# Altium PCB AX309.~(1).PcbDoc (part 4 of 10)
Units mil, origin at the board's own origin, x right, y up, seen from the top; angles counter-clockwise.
Board outline 5185 x 3614 mil, 4 copper layers (Top Layer, GND, Mid-Layer 1, Bottom Layer); 191 components, 352 nets, 1106 pads, 425 vias.
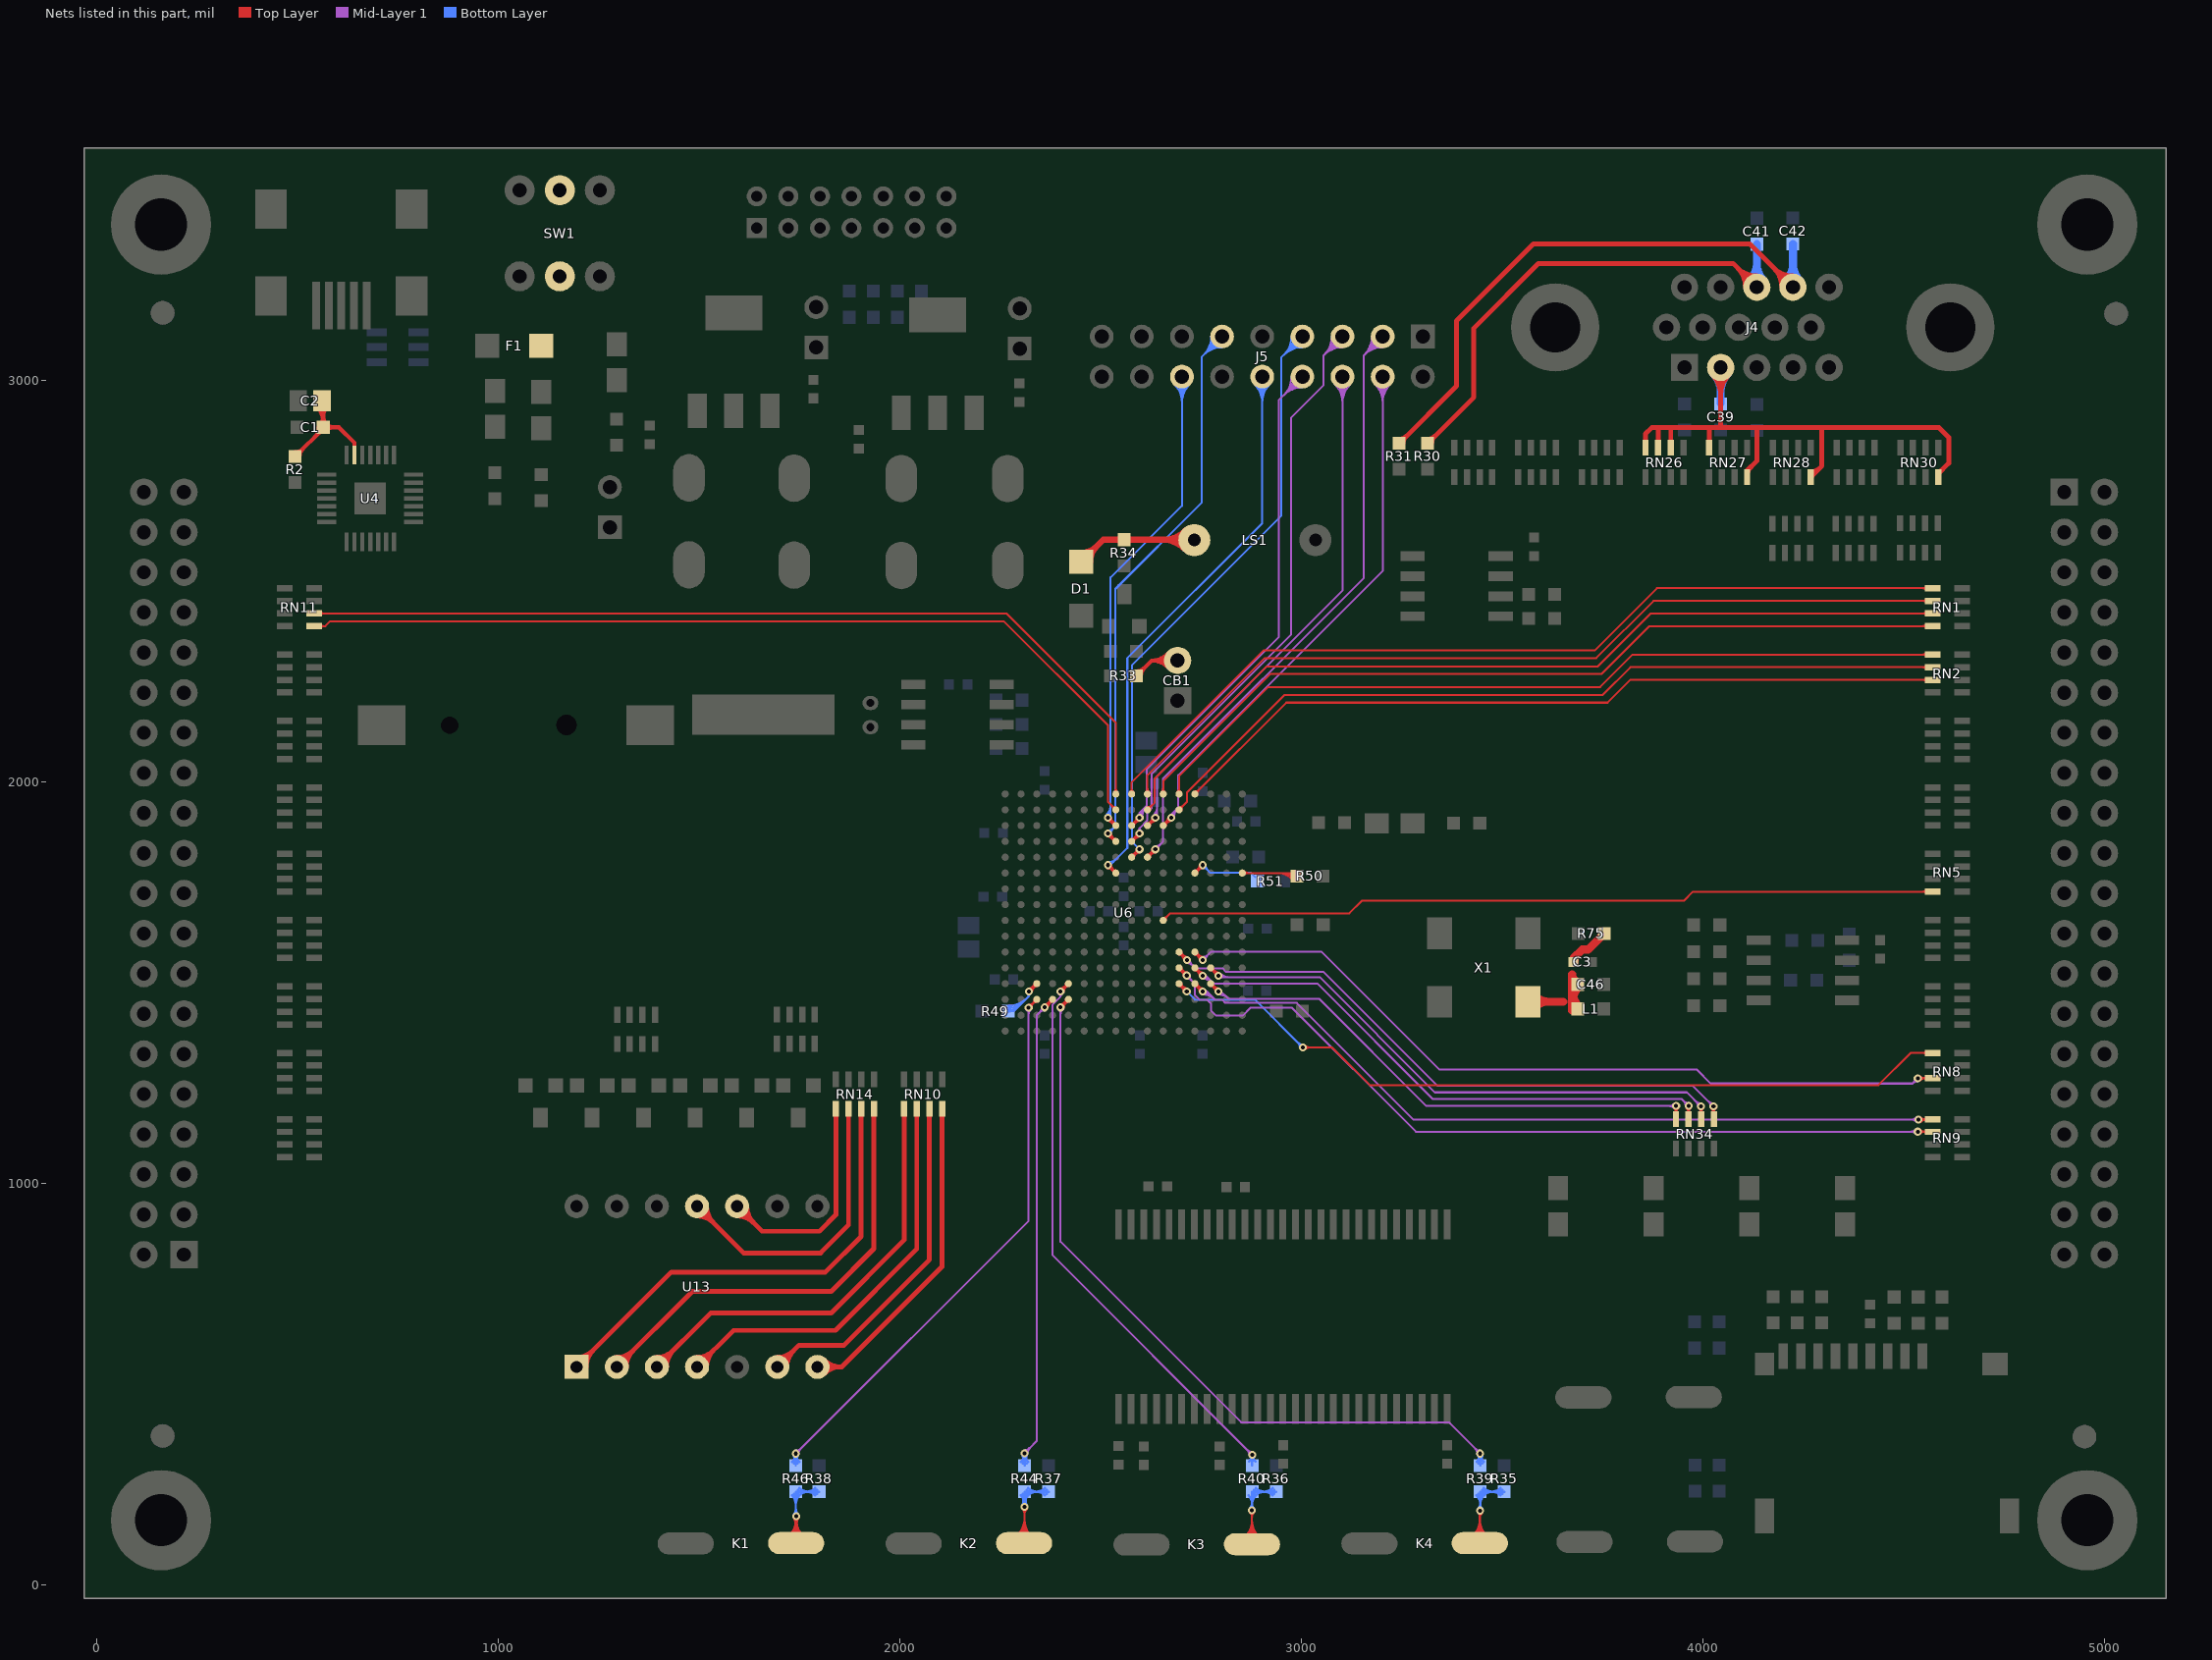
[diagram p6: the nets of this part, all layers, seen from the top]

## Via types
v1: diameter 20, hole 10, Top Layer to Bottom Layer, 328 vias
v2: diameter 30, hole 15, Top Layer to Bottom Layer, 95 vias
v3: diameter 40, hole 20, Top Layer to Bottom Layer, 2 vias

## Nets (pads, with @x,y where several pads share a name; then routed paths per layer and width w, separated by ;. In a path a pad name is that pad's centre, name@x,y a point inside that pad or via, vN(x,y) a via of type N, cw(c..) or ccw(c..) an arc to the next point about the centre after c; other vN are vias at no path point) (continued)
GREEN: C39.1 J4.2 RN26.2 RN26.3 RN26.4 RN27.4 RN27.8 RN28.8 RN30.8 | length 1876.1
  Top Layer w12: RN26.4@3857.65,2832 3857.65,2866.65 3873,2882 4135,2882 ; RN26.3@3889.15,2832 3889.15,2880.15 ; RN26.2@3920.65,2832 3920.65,2881.65 ; RN27.4@4016.37,2832 4016.37,2880.37 ; J4.2@4025.2,3012.2 cw(c3977.4,2964.4) 4045,2964.4 cw(c4112.6,2964.4) J4.2@4064.8,3012.2 ; J4.2@4033.69,3020.69 cw(c4006.37,2993.37) 4045,2993.37 cw(c4083.63,2993.37) J4.2@4056.31,3020.69 ; 4045,2883 J4.2@4045,3032 ; RN27.8@4110.86,2758.85 4110.86,2774.86 4135,2799 4135,2882 ; RN27.8@4112.73,2770.66 cw(c4127.38,2770.66) 4117.02,2781.02 ; RN28.8@4269.57,2758.85 4297,2786.28 4297,2882 ; RN28.8@4269.57,2760.54 ccw(c4269.57,2764.6) RN28.8@4272.45,2761.73 ; RN28.8@4269.57,2772.54 ccw(c4269.57,2805.57) 4292.93,2782.21 ; RN30.8@4587,2758.85 4587,2767.5 4613,2793.5 4613,2858 4589,2882 4297,2882 ; RN30.8@4587,2772.54 ccw(c4587,2784.69) 4595.59,2776.1 ; 4135,2882 4297,2882
  Bottom Layer w20: J4.2@4028.03,3015.03 cw(c3987.06,2974.06) 4045,2974.06 cw(c4102.94,2974.06) J4.2@4061.97,3015.03 ; C39.1@4045,2943 J4.2@4045,3032
H11: J5.10 U6.H11 | length 1849.8
  Top Layer w5: v1@2517.62,1784.68 cw(c2514.91,1764.7) U6.H11@2532.37,1774.78 ; v1@2518.29,1789.63 cw(c2516.64,1777.47) 2527.27,1783.61 ; v1@2518.63,1784.61 cw(c2518.63,1766.5) 2531.43,1779.31 cw(c2544.24,1792.11) v1@2526.13,1792.11 ; v1(2518.63,1792.11) U6.H11@2538.32,1772.43 ; v1@2520.6,1784.87 cw(c2522.41,1778.21) 2528.39,1781.66 ; v1@2521.11,1792.45 ccw(c2533.27,1794.1) 2527.13,1783.47 ; v1@2526.06,1793.12 ccw(c2546.04,1795.83) U6.H11@2535.96,1778.37 ; 2529.08,1782.35 cw(c2532.53,1788.33) v1@2525.87,1790.14 ; U6.H11@2531.96,1772.43 ccw(c2516.61,1772.43) 2527.46,1783.28 ccw(c2538.32,1794.13) U6.H11@2538.32,1778.78 ; v1@2525.87,1790.17 ccw(c2532.7,1788.34) 2526.58,1784.81 cw(c2532.7,1788.34) v1@2525.87,1790.17 ; v1@2520.57,1784.87 cw(c2522.4,1778.04) 2525.93,1784.16 ccw(c2522.4,1778.04) v1@2520.57,1784.87
  Bottom Layer w5: v1(2518.63,1792.11) 2524.11,1792.11 2567,1835 2567,2308 2903,2644 J5.10@2903,3009.17 ; v1@2518.63,1794.61 ccw(c2518.63,1813.88) 2532.26,1800.26 ; v1@2518.63,1799.61 ccw(c2518.63,1830.95) 2540.79,1808.79 ; J5.10@2883.89,2990.06 cw(c2837.75,2943.92) 2903,2943.92 cw(c2968.25,2943.92) J5.10@2922.11,2990.06 ; J5.10@2887.42,2993.6 cw(c2849.82,2955.99) 2903,2955.99 cw(c2956.18,2955.99) J5.10@2918.58,2993.6 ; J5.10@2890.96,2997.13 cw(c2861.89,2968.07) 2903,2968.07 cw(c2944.11,2968.07) J5.10@2915.04,2997.13
H13: J5.11 U6.H13 | length 1815.1
  Top Layer w5: v1@2517.62,1863.42 cw(c2514.91,1843.44) U6.H13@2532.37,1853.52 ; v1@2518.29,1868.37 cw(c2516.64,1856.21) 2527.27,1862.35 ; v1@2518.63,1863.35 cw(c2518.63,1845.24) 2531.43,1858.05 cw(c2544.24,1870.85) v1@2526.13,1870.85 ; v1(2518.63,1870.85) U6.H13@2538.32,1851.17 ; v1@2520.6,1863.61 cw(c2522.41,1856.95) 2528.39,1860.4 ; v1@2521.11,1871.19 ccw(c2533.27,1872.84) 2527.13,1862.21 ; v1@2526.06,1871.86 ccw(c2546.04,1874.57) U6.H13@2535.96,1857.11 ; 2529.08,1861.09 cw(c2532.53,1867.07) v1@2525.87,1868.88 ; U6.H13@2531.96,1851.17 ccw(c2516.61,1851.17) 2527.46,1862.02 ccw(c2538.32,1872.87) U6.H13@2538.32,1857.52 ; v1@2525.87,1868.91 ccw(c2532.7,1867.08) 2526.58,1863.55 cw(c2532.7,1867.08) v1@2525.87,1868.91 ; v1@2520.57,1863.61 cw(c2522.4,1856.78) 2525.93,1862.9 ccw(c2522.4,1856.78) v1@2520.57,1863.61
  Bottom Layer w5: v1(2518.63,1870.85) 2537,1889.22 2537,2480 2752,2695 2752,3058.17 J5.11@2803,3109.17 ; v1@2518.63,1878.35 ccw(c2518.63,1896.46) 2531.43,1883.65 ccw(c2544.24,1870.85) v1@2526.13,1870.85 ; J5.11@2775.97,3109.17 cw(c2710.72,3109.17) 2756.86,3063.03 cw(c2803,3016.9) J5.11@2803,3082.15 ; J5.11@2780.97,3109.17 cw(c2727.79,3109.17) 2765.4,3071.57 cw(c2803,3033.97) J5.11@2803,3087.15 ; J5.11@2785.97,3109.17 cw(c2744.86,3109.17) 2773.93,3080.11 cw(c2803,3051.04) J5.11@2803,3092.15
H14: J5.14 U6.H14 | length 1671.3
  Top Layer w5: v1@2517.62,1902.79 cw(c2514.91,1882.81) U6.H14@2532.37,1892.89 ; v1@2518.29,1907.74 cw(c2516.64,1895.58) 2527.27,1901.72 ; v1@2518.63,1902.72 cw(c2518.63,1884.61) 2531.43,1897.42 cw(c2544.24,1910.22) v1@2526.13,1910.22 ; v1(2518.63,1910.22) U6.H14@2538.32,1890.54 ; v1@2520.6,1902.98 cw(c2522.41,1896.32) 2528.39,1899.77 ; v1@2521.11,1910.56 ccw(c2533.27,1912.21) 2527.13,1901.58 ; v1@2525.87,1908.25 ccw(c2532.53,1906.44) 2529.08,1900.46 ; v1@2526.06,1911.23 ccw(c2546.04,1913.94) U6.H14@2535.96,1896.48 ; U6.H14@2531.96,1890.54 ccw(c2516.61,1890.54) 2527.46,1901.39 ccw(c2538.32,1912.24) U6.H14@2538.32,1896.89 ; v1@2520.57,1902.98 cw(c2522.4,1896.15) 2525.93,1902.27 ccw(c2522.4,1896.15) v1@2520.57,1902.98 ; v1@2525.87,1908.28 ccw(c2532.7,1906.45) 2526.58,1902.92 cw(c2532.7,1906.45) v1@2525.87,1908.28
  Bottom Layer w5: v1@2513.33,1915.52 ccw(c2485.14,1943.71) 2525,1943.71 ; v1@2516.86,1911.99 ccw(c2497.21,1931.64) 2525,1931.64 ; v1(2518.63,1910.22) 2525,1916.59 2525,2509 2703,2687 J5.14@2703,3009.17 ; v1@2520.4,1908.45 ccw(c2509.28,1919.57) 2525,1919.57 ; J5.14@2683.89,2990.06 cw(c2637.75,2943.92) 2703,2943.92 cw(c2768.25,2943.92) J5.14@2722.11,2990.06 ; J5.14@2687.42,2993.6 cw(c2649.82,2955.99) 2703,2955.99 cw(c2756.18,2955.99) J5.14@2718.58,2993.6 ; J5.14@2690.96,2997.13 cw(c2661.89,2968.07) 2703,2968.07 cw(c2744.11,2968.07) J5.14@2715.04,2997.13
H15: RN11.5 U6.H15 | length 2352.5
  Top Layer w5: RN11.5@541.15,2387.51 568.84,2387.51 580.32,2399 2260,2399 2519,2140 2519,1949.22 U6.H15@2538.32,1929.91 ; RN11.5@556.76,2383.71 cw(c565.93,2374.54) 565.93,2387.51 cw(c565.93,2400.49) RN11.5@556.76,2391.31 ; U6.H15@2531.96,1929.91 ccw(c2516.61,1929.91) 2527.46,1940.76 ccw(c2538.32,1951.61) U6.H15@2538.32,1936.26
H16: RN11.6 U6.H16 | length 2331.9
  Top Layer w5: RN11.6@541.15,2419.01 2265.99,2419.01 2538.32,2146.68 U6.H16@2538.32,1969.28 ; RN11.6@556.76,2415.21 cw(c565.93,2406.03) 565.93,2419.01 cw(c565.93,2431.98) RN11.6@556.76,2422.81 ; U6.H16@2533.82,1973.77 ccw(c2522.96,1984.63) 2538.32,1984.63 ccw(c2553.67,1984.63) U6.H16@2542.81,1973.77
HSWAPEN: R49.1 U6.C4 | length 421.8
  Top Layer w5: v1@2320.77,1484.58 ccw(c2318.06,1504.56) U6.C4@2335.52,1494.48 ; v1@2321.44,1479.63 ccw(c2319.79,1491.79) 2330.42,1485.65 ; v1(2321.78,1477.15) U6.C4@2341.46,1496.83 ; v1@2321.78,1484.65 ccw(c2321.78,1502.76) 2334.58,1489.95 ccw(c2347.39,1477.15) v1@2329.28,1477.15 ; v1@2323.75,1484.39 ccw(c2325.56,1491.05) 2331.54,1487.6 ; v1@2324.26,1476.81 cw(c2336.42,1475.16) 2330.28,1485.79 ; v1@2329.21,1476.14 cw(c2349.19,1473.43) U6.C4@2339.11,1490.89 ; 2332.23,1486.91 ccw(c2335.68,1480.93) v1@2329.02,1479.12 ; U6.C4@2335.11,1496.83 cw(c2319.76,1496.83) 2330.61,1485.98 cw(c2341.46,1475.13) U6.C4@2341.46,1490.48 ; v1@2329.02,1479.09 cw(c2335.85,1480.92) 2329.73,1484.45 ccw(c2335.85,1480.92) v1@2329.02,1479.09 ; v1@2323.72,1484.39 ccw(c2325.55,1491.22) 2329.08,1485.1 cw(c2325.55,1491.22) v1@2323.72,1484.39
  Bottom Layer w5: R49.1@2270,1426.5 ccw(c2270,1456.68) 2291.34,1435.34 ; R49.1@2270,1428 2284,1428 2321.78,1465.78 ; R49.1@2270,1431.5 ccw(c2270,1473.75) 2299.87,1443.87 ; R49.1@2270,1436.5 ccw(c2270,1490.82) 2308.41,1452.41 ; R49.1@2270,1441.5 ccw(c2270,1507.89) 2316.95,1460.95 ; v1@2318.83,1470.25 cw(c2316.91,1465.78) 2321.78,1465.78 ; v1(2321.78,1477.15) 2321.78,1465.78 ; v1@2324.73,1470.25 ccw(c2326.65,1465.78) 2321.78,1465.78
J12: J5.7 U6.J12 | length 1891.4
  Top Layer w5: U6.J12@2577.68,1811.8 v1(2597.37,1831.48) ; U6.J12@2577.68,1818.15 ccw(c2577.68,1833.5) 2588.54,1822.65 ccw(c2599.39,1811.8) U6.J12@2584.04,1811.8 ; U6.J12@2580.04,1817.74 ccw(c2569.96,1835.2) v1@2589.94,1832.49 ; U6.J12@2583.63,1814.15 cw(c2601.09,1804.07) v1@2598.38,1824.05 ; 2586.92,1821.72 ccw(c2583.47,1827.7) v1@2590.13,1829.51 ; 2587.61,1821.03 cw(c2593.59,1817.58) v1@2595.4,1824.24 ; 2588.73,1822.98 cw(c2599.36,1816.84) v1@2597.71,1829 ; 2588.87,1822.84 ccw(c2582.73,1833.47) v1@2594.89,1831.82 ; v1@2589.87,1831.48 cw(c2571.76,1831.48) 2584.57,1818.68 cw(c2597.37,1805.87) v1@2597.37,1823.98 ; 2589.42,1824.18 ccw(c2583.3,1827.71) 2590.13,1829.54 cw(c2583.3,1827.71) 2589.42,1824.18 ; 2590.07,1823.53 cw(c2593.6,1817.41) 2595.43,1824.24 ccw(c2593.6,1817.41) 2590.07,1823.53
  Bottom Layer w5: v1(2597.37,1831.48) 2579,1849.85 2579,2291 2950,2662 2950,3056.17 J5.7@3003,3109.17 ; J5.7@2975.97,3109.17 cw(c2910.72,3109.17) 2956.86,3063.03 cw(c3003,3016.9) J5.7@3003,3082.15 ; J5.7@2980.97,3109.17 cw(c2927.79,3109.17) 2965.4,3071.57 cw(c3003,3033.97) J5.7@3003,3087.15 ; J5.7@2985.97,3109.17 cw(c2944.86,3109.17) 2973.93,3080.11 cw(c3003,3051.04) J5.7@3003,3092.15
J13: J5.5 U6.J13 | length 1895.4
  Top Layer w5: U6.J13@2577.68,1851.17 v1(2597.37,1870.85) ; U6.J13@2577.68,1857.52 ccw(c2577.68,1872.87) 2588.54,1862.02 ccw(c2599.39,1851.17) U6.J13@2584.04,1851.17 ; U6.J13@2580.04,1857.11 ccw(c2569.96,1874.57) v1@2589.94,1871.86 ; U6.J13@2583.63,1853.52 cw(c2601.09,1843.44) v1@2598.38,1863.42 ; 2586.92,1861.09 ccw(c2583.47,1867.07) v1@2590.13,1868.88 ; 2587.61,1860.4 cw(c2593.59,1856.95) v1@2595.4,1863.61 ; 2588.73,1862.35 cw(c2599.36,1856.21) v1@2597.71,1868.37 ; 2588.87,1862.21 ccw(c2582.73,1872.84) v1@2594.89,1871.19 ; v1@2589.87,1870.85 cw(c2571.76,1870.85) 2584.57,1858.05 cw(c2597.37,1845.24) v1@2597.37,1863.35 ; v1@2590.13,1868.91 cw(c2583.3,1867.08) 2589.42,1863.55 ccw(c2583.3,1867.08) v1@2590.13,1868.91 ; 2590.07,1862.9 cw(c2593.6,1856.78) 2595.43,1863.61 ccw(c2593.6,1856.78) 2590.07,1862.9
  Mid-Layer 1 w5: v1@2593.4,1877.21 ccw(c2588.94,1884.37) 2597.37,1884.37 ; v1(2597.37,1870.85) 2597.37,1884.37 ; v1@2601.34,1877.21 cw(c2605.81,1884.37) 2597.37,1884.37 ; J5.5@3075.97,3109.17 cw(c3010.72,3109.17) 3056.86,3063.03 cw(c3103,3016.9) J5.5@3103,3082.15 ; J5.5@3080.97,3109.17 cw(c3027.79,3109.17) 3065.4,3071.57 cw(c3103,3033.97) J5.5@3103,3087.15 ; J5.5@3085.97,3109.17 cw(c3044.86,3109.17) 3073.93,3080.11 cw(c3103,3051.04) J5.5@3103,3092.15 ; J5.5@3103,3109.17 3055,3061.17 3055,2987 2975,2907 2975,2367 2628,2020 2628,1934 2616,1922 2616,1903 2597.37,1884.37
J14: J5.8 U6.J14 | length 1783.8
  Top Layer w5: U6.J14@2577.68,1890.54 v1(2597.37,1910.22) ; U6.J14@2577.68,1896.89 ccw(c2577.68,1912.24) 2588.54,1901.39 ccw(c2599.39,1890.54) U6.J14@2584.04,1890.54 ; U6.J14@2580.04,1896.48 ccw(c2569.96,1913.94) v1@2589.94,1911.23 ; U6.J14@2583.63,1892.89 cw(c2601.09,1882.81) v1@2598.38,1902.79 ; 2586.92,1900.46 ccw(c2583.47,1906.44) v1@2590.13,1908.25 ; 2587.61,1899.77 cw(c2593.59,1896.32) v1@2595.4,1902.98 ; 2588.73,1901.72 cw(c2599.36,1895.58) v1@2597.71,1907.74 ; 2588.87,1901.58 ccw(c2582.73,1912.21) v1@2594.89,1910.56 ; v1@2589.87,1910.22 cw(c2571.76,1910.22) 2584.57,1897.42 cw(c2597.37,1884.61) v1@2597.37,1902.72 ; 2589.42,1902.92 ccw(c2583.3,1906.45) 2590.13,1908.28 cw(c2583.3,1906.45) 2589.42,1902.92 ; 2590.07,1902.27 cw(c2593.6,1896.15) 2595.43,1902.98 ccw(c2593.6,1896.15) 2590.07,1902.27
  Mid-Layer 1 w5: v1@2594.01,1916.93 ccw(c2591.28,1922.37) 2597.37,1922.37 ; v1@2594.89,1909.95 cw(c2613.54,1912) 2600.27,1925.27 ; v1(2597.37,1910.22) 2597.37,1922.37 ; v1@2599.86,1910.5 cw(c2626.8,1913.46) 2607.63,1932.63 ; v1@2600.73,1916.93 cw(c2603.46,1922.37) 2597.37,1922.37 ; v1@2604.83,1911.04 cw(c2640.07,1914.92) 2615,1940 ; J5.8@2975.97,3009.17 cw(c2910.72,3009.17) 2956.86,2963.03 cw(c3003,2916.9) J5.8@3003,2982.15 ; J5.8@2980.97,3009.17 cw(c2927.79,3009.17) 2965.4,2971.57 cw(c3003,2933.97) J5.8@3003,2987.15 ; J5.8@2985.97,3009.17 cw(c2944.86,3009.17) 2973.93,2980.11 cw(c3003,2951.04) J5.8@3003,2992.15 ; J5.8@3003,3009.17 2944,2950.17 2944,2360 2615,2031 2615,1940 ; 2597.37,1922.37 2615,1940
J16: RN1.1 U6.J16 | length 2269.4
  Top Layer w5: U6.J16@2573.19,1973.77 ccw(c2562.33,1984.63) 2577.68,1984.63 ccw(c2593.04,1984.63) U6.J16@2582.18,1973.77 ; U6.J16@2577.68,1969.28 2577.68,1998.68 2906,2327 3731,2327 3886,2482 RN1.1@4573,2482 ; RN1.1@4557.39,2478.2 ccw(c4548.22,2469.03) 4548.22,2482 ccw(c4548.22,2494.97) RN1.1@4557.39,2485.8
K12: J5.3 U6.K12 | length 1971.2
  Top Layer w5: U6.K12@2617.06,1811.8 v1(2636.74,1831.48) ; U6.K12@2617.06,1818.15 ccw(c2617.06,1833.5) 2627.91,1822.65 ccw(c2638.76,1811.8) U6.K12@2623.41,1811.8 ; U6.K12@2619.41,1817.74 ccw(c2609.33,1835.2) v1@2629.31,1832.49 ; U6.K12@2623,1814.15 cw(c2640.46,1804.07) v1@2637.75,1824.05 ; 2626.29,1821.72 ccw(c2622.84,1827.7) v1@2629.5,1829.51 ; 2626.98,1821.03 cw(c2632.96,1817.58) v1@2634.77,1824.24 ; 2628.1,1822.98 cw(c2638.73,1816.84) v1@2637.08,1829 ; 2628.24,1822.84 ccw(c2622.1,1833.47) v1@2634.26,1831.82 ; v1@2629.24,1831.48 cw(c2611.13,1831.48) 2623.94,1818.68 cw(c2636.74,1805.87) v1@2636.74,1823.98 ; 2628.79,1824.18 ccw(c2622.67,1827.71) 2629.5,1829.54 cw(c2622.67,1827.71) 2628.79,1824.18 ; 2629.44,1823.53 cw(c2632.97,1817.41) 2634.8,1824.24 ccw(c2632.97,1817.41) 2629.44,1823.53
  Mid-Layer 1 w5: v1(2636.74,1831.48) 2656,1850.74 2656,2008 3156,2508 3156,3062.17 J5.3@3203,3109.17 ; v1@2636.74,1838.98 ccw(c2636.74,1857.09) 2649.54,1844.28 ccw(c2662.35,1831.48) v1@2644.24,1831.48 ; J5.3@3175.97,3109.17 cw(c3110.72,3109.17) 3156.86,3063.03 cw(c3203,3016.9) J5.3@3203,3082.15 ; J5.3@3180.97,3109.17 cw(c3127.79,3109.17) 3165.4,3071.57 cw(c3203,3033.97) J5.3@3203,3087.15 ; J5.3@3185.97,3109.17 cw(c3144.86,3109.17) 3173.93,3080.11 cw(c3203,3051.04) J5.3@3203,3092.15
K14: J5.6 U6.K14 | length 1764.4
  Top Layer w5: U6.K14@2617.06,1890.54 v1(2636.74,1910.22) ; U6.K14@2617.06,1896.89 ccw(c2617.06,1912.24) 2627.91,1901.39 ccw(c2638.76,1890.54) U6.K14@2623.41,1890.54 ; U6.K14@2619.41,1896.48 ccw(c2609.33,1913.94) v1@2629.31,1911.23 ; U6.K14@2623,1892.89 cw(c2640.46,1882.81) v1@2637.75,1902.79 ; 2626.29,1900.46 ccw(c2622.84,1906.44) v1@2629.5,1908.25 ; 2626.98,1899.77 cw(c2632.96,1896.32) v1@2634.77,1902.98 ; 2628.1,1901.72 cw(c2638.73,1895.58) v1@2637.08,1907.74 ; 2628.24,1901.58 ccw(c2622.1,1912.21) v1@2634.26,1910.56 ; v1@2629.24,1910.22 cw(c2611.13,1910.22) 2623.94,1897.42 cw(c2636.74,1884.61) v1@2636.74,1902.72 ; 2628.79,1902.92 ccw(c2622.67,1906.45) 2629.5,1908.28 cw(c2622.67,1906.45) 2628.79,1902.92 ; 2629.44,1902.27 cw(c2632.97,1896.15) 2634.8,1902.98 ccw(c2632.97,1896.15) 2629.44,1902.27
  Mid-Layer 1 w5: v1@2631.44,1915.52 ccw(c2608.35,1938.61) 2641,1938.61 ; v1@2634.97,1911.99 ccw(c2620.42,1926.54) 2641,1926.54 ; v1(2636.74,1910.22) 2641,1914.48 2641,2014 3103,2476 J5.6@3103,3009.17 ; J5.6@3083.89,2990.06 cw(c3037.75,2943.92) 3103,2943.92 cw(c3168.25,2943.92) J5.6@3122.11,2990.06 ; J5.6@3087.42,2993.6 cw(c3049.82,2955.99) 3103,2955.99 cw(c3156.18,2955.99) J5.6@3118.58,2993.6 ; J5.6@3090.96,2997.13 cw(c3061.89,2968.07) 3103,2968.07 cw(c3144.11,2968.07) J5.6@3115.04,2997.13
K15: RN1.3 U6.K15 | length 2238.3
  Top Layer w5: U6.K15@2617.06,1929.91 2635,1947.85 2635,2008 2914,2287 3739,2287 3871.01,2419.01 RN1.3@4573,2419.01 ; U6.K15@2617.06,1936.26 ccw(c2617.06,1951.61) 2627.91,1940.76 ccw(c2638.76,1929.91) U6.K15@2623.41,1929.91 ; RN1.3@4557.39,2415.21 ccw(c4548.22,2406.03) 4548.22,2419.01 ccw(c4548.22,2431.98) RN1.3@4557.39,2422.81
K16: RN1.2 U6.K16 | length 2227.2
  Top Layer w5: U6.K16@2612.56,1973.77 ccw(c2601.7,1984.63) 2617.06,1984.63 ccw(c2632.41,1984.63) U6.K16@2621.55,1973.77 ; U6.K16@2617.06,1969.28 2617.06,2016.06 2909,2308 3735,2308 3877.5,2450.5 RN1.2@4573,2450.5 ; RN1.2@4557.39,2446.7 ccw(c4548.22,2437.53) 4548.22,2450.5 ccw(c4548.22,2463.48) RN1.2@4557.39,2454.3
KEY1: R46.1 U6.C3 | length 1658.6
  Top Layer w5: v1(2321,1437) U6.C3@2341.46,1457.46 ; v1@2321,1444.5 ccw(c2321,1462.61) 2333.8,1449.8 ccw(c2346.61,1437) v1@2328.5,1437 ; U6.C3@2335.11,1457.46 cw(c2319.76,1457.46) 2330.61,1446.61 cw(c2341.46,1435.76) U6.C3@2341.46,1451.11
  Mid-Layer 1 w5: v1(1741,326) 2321,906 v1(2321,1437) ; v1@1741,333.5 ccw(c1741,351.61) 1753.8,338.8 ccw(c1766.61,326) v1@1748.5,326 ; v1@2315.7,1431.7 cw(c2302.89,1418.89) 2321,1418.89 cw(c2339.11,1418.89) v1@2326.3,1431.7
  Bottom Layer w6: R46.1@1732.11,305.49 ccw(c1712.89,326) v1(1741,326) ; v1@1735.36,321.85 cw(c1726,314.95) 1737.23,311.94 cw(c1748.47,308.93) v1@1743.81,319.59 ; v1@1736.05,321.05 cw(c1724.1,309.1) 1741,309.1 cw(c1757.9,309.1) v1@1745.95,321.05 ; R46.1@1736.21,301.11 ccw(c1725.86,312.15) 1741,312.15 ccw(c1756.14,312.15) R46.1@1745.79,301.11 ; v1@1738.19,319.59 cw(c1733.53,308.93) 1744.77,311.94 cw(c1756,314.95) v1@1746.64,321.85 ; R46.1@1741,296 v1(1741,326) ; R46.1@1749.89,305.49 cw(c1769.11,326) v1(1741,326)
KEY2: R44.1 U6.D3 | length 1546.1
  Top Layer w5: v1@2360.14,1445.21 ccw(c2357.43,1465.19) U6.D3@2374.89,1455.11 ; v1@2360.81,1440.26 ccw(c2359.16,1452.42) 2369.79,1446.28 ; v1(2361.15,1437.78) U6.D3@2380.83,1457.46 ; v1@2361.15,1445.28 ccw(c2361.15,1463.39) 2373.95,1450.58 ccw(c2386.76,1437.78) v1@2368.65,1437.78 ; v1@2363.63,1437.44 cw(c2375.79,1435.79) 2369.65,1446.42 ; v1@2368.39,1439.75 cw(c2375.05,1441.56) 2371.6,1447.54 ; v1@2368.58,1436.77 cw(c2388.56,1434.06) U6.D3@2378.48,1451.52 ; 2370.91,1448.23 cw(c2364.93,1451.68) v1@2363.12,1445.02 ; U6.D3@2374.48,1457.46 cw(c2359.13,1457.46) 2369.98,1446.61 cw(c2380.83,1435.76) U6.D3@2380.83,1451.11 ; v1@2363.09,1445.02 ccw(c2364.92,1451.85) 2368.45,1445.73 cw(c2364.92,1451.85) v1@2363.09,1445.02 ; v1@2368.39,1439.72 cw(c2375.22,1441.55) 2369.1,1445.08 ccw(c2375.22,1441.55) v1@2368.39,1439.72
  Mid-Layer 1 w5: 2323.37,339.37 2341.46,357.46 2341.46,1418.09 v1(2361.15,1437.78) ; v1@2353.65,1437.78 cw(c2335.54,1437.78) 2348.35,1424.98 cw(c2361.15,1412.17) v1@2361.15,1430.28
  Mid-Layer 1 w6: v1(2311,327) 2323.37,339.37 ; v1@2311,334 ccw(c2311,350.9) 2322.95,338.95 ccw(c2334.9,327) v1@2318,327
  Bottom Layer w6: R44.1@2301.89,305.27 ccw(c2280.54,327) v1(2311,327) ; v1@2305.12,323.2 cw(c2293.15,315.46) 2306.92,311.77 cw(c2320.69,308.08) v1@2314.19,320.77 ; v1@2306.05,322.05 cw(c2294.1,310.1) 2311,310.1 cw(c2327.9,310.1) v1@2315.95,322.05 ; R44.1@2306.09,300.99 ccw(c2294.6,312.69) 2311,312.69 ccw(c2327.4,312.69) R44.1@2315.91,300.99 ; v1@2307.81,320.77 cw(c2301.31,308.08) 2315.08,311.77 cw(c2328.85,315.46) v1@2316.88,323.2 ; R44.1@2311,296 v1(2311,327) ; R44.1@2320.11,305.27 cw(c2341.46,327) v1(2311,327)
KEY3: R40.1 U6.E4 | length 1708.4
  Top Layer w5: v1@2399.51,1484.58 ccw(c2396.8,1504.56) U6.E4@2414.26,1494.48 ; v1@2400.18,1479.63 ccw(c2398.53,1491.79) 2409.16,1485.65 ; v1(2400.52,1477.15) U6.E4@2420.2,1496.83 ; v1@2400.52,1484.65 ccw(c2400.52,1502.76) 2413.32,1489.95 ccw(c2426.13,1477.15) v1@2408.02,1477.15 ; v1@2402.49,1484.39 ccw(c2404.3,1491.05) 2410.28,1487.6 ; v1@2403,1476.81 cw(c2415.16,1475.16) 2409.02,1485.79 ; v1@2407.95,1476.14 cw(c2427.93,1473.43) U6.E4@2417.85,1490.89 ; 2410.97,1486.91 ccw(c2414.42,1480.93) v1@2407.76,1479.12 ; U6.E4@2413.85,1496.83 cw(c2398.5,1496.83) 2409.35,1485.98 cw(c2420.2,1475.13) U6.E4@2420.2,1490.48 ; v1@2407.76,1479.09 cw(c2414.59,1480.92) 2408.47,1484.45 ccw(c2414.59,1480.92) v1@2407.76,1479.09 ; v1@2402.46,1484.39 ccw(c2404.29,1491.22) 2407.82,1485.1 cw(c2404.29,1491.22) v1@2402.46,1484.39
  Mid-Layer 1 w5: v1@2396.93,1470.56 cw(c2393.64,1464.52) 2400.52,1464.52 ; v1(2400.52,1477.15) 2400.52,1464.52 ; v1@2404.11,1470.56 ccw(c2407.4,1464.52) 2400.52,1464.52 ; v1@2870.5,323 ccw(c2852.39,323) 2865.2,335.8 ccw(c2878,348.61) v1@2878,330.5 ; v1(2878,323) 2380,821 2380,1444 2400.52,1464.52
  Bottom Layer w6: R40.1@2869.89,306.16 ccw(c2856.46,323) v1(2878,323) ; v1@2873.05,318.05 cw(c2861.1,306.1) 2878,306.1 cw(c2894.9,306.1) v1@2882.95,318.05 ; v1@2873.43,317.7 cw(c2869.92,313.62) 2875.11,312.23 cw(c2880.31,310.84) v1@2879.31,316.12 ; v1@2876.69,316.12 cw(c2875.69,310.84) 2880.89,312.23 cw(c2886.08,313.62) v1@2882.57,317.7 ; R40.1@2878,296 v1(2878,323) ; R40.1@2886.11,306.16 cw(c2899.54,323) v1(2878,323)
KEY4: R39.1 U6.E3 | length 2253.7
  Top Layer w5: v1@2399.51,1445.21 ccw(c2396.8,1465.19) U6.E3@2414.26,1455.11 ; v1@2400.18,1440.26 ccw(c2398.53,1452.42) 2409.16,1446.28 ; v1(2400.52,1437.78) U6.E3@2420.2,1457.46 ; v1@2400.52,1445.28 ccw(c2400.52,1463.39) 2413.32,1450.58 ccw(c2426.13,1437.78) v1@2408.02,1437.78 ; v1@2402.49,1445.02 ccw(c2404.3,1451.68) 2410.28,1448.23 ; v1@2403,1437.44 cw(c2415.16,1435.79) 2409.02,1446.42 ; v1@2407.76,1439.75 cw(c2414.42,1441.56) 2410.97,1447.54 ; v1@2407.95,1436.77 cw(c2427.93,1434.06) U6.E3@2417.85,1451.52 ; U6.E3@2413.85,1457.46 cw(c2398.5,1457.46) 2409.35,1446.61 cw(c2420.2,1435.76) U6.E3@2420.2,1451.11 ; v1@2402.46,1445.02 ccw(c2404.29,1451.85) 2407.82,1445.73 cw(c2404.29,1451.85) v1@2402.46,1445.02 ; v1@2407.76,1439.72 cw(c2414.59,1441.55) 2408.47,1445.08 ccw(c2414.59,1441.55) v1@2407.76,1439.72
  Mid-Layer 1 w5: v1@2395.22,1432.48 cw(c2382.41,1419.67) 2400.52,1419.67 cw(c2418.63,1419.67) v1@2405.82,1432.48 ; v1(2400.52,1437.78) 2400.52,854.06 2850.58,404 3368,404 v1(3446,326) ; v1@3438.5,326 ccw(c3420.39,326) 3433.2,338.8 ccw(c3446,351.61) v1@3446,333.5
  Bottom Layer w6: R39.1@3437.11,305.49 ccw(c3417.89,326) v1(3446,326) ; v1@3440.36,321.85 cw(c3431,314.95) 3442.23,311.94 cw(c3453.47,308.93) v1@3448.81,319.59 ; v1@3441.05,321.05 cw(c3429.1,309.1) 3446,309.1 cw(c3462.9,309.1) v1@3450.95,321.05 ; R39.1@3441.21,301.11 ccw(c3430.86,312.15) 3446,312.15 ccw(c3461.14,312.15) R39.1@3450.79,301.11 ; v1@3443.19,319.59 cw(c3438.53,308.93) 3449.77,311.94 cw(c3461,314.95) v1@3451.64,321.85 ; R39.1@3446,296 v1(3446,326) ; R39.1@3454.89,305.49 cw(c3474.11,326) v1(3446,326)
L8: RN5.4 U6.L8 | length 1990.8
  Top Layer w5: U6.L8@2656.43,1654.32 2674.11,1672 3120,1672 3151,1703 3953,1703 3976.01,1726.01 RN5.4@4573,1726.01 ; U6.L8@2656.43,1660.67 ccw(c2656.43,1676.02) 2667.28,1665.17 ccw(c2678.13,1654.32) U6.L8@2662.78,1654.32 ; RN5.4@4557.39,1722.21 ccw(c4548.22,1713.04) 4548.22,1726.01 ccw(c4548.22,1738.99) RN5.4@4557.39,1729.81
L14: J5.4 U6.L14 | length 1795.2
  Top Layer w5: U6.L14@2656.43,1890.54 v1(2676.11,1910.22) ; U6.L14@2656.43,1896.89 ccw(c2656.43,1912.24) 2667.28,1901.39 ccw(c2678.13,1890.54) U6.L14@2662.78,1890.54 ; U6.L14@2658.78,1896.48 ccw(c2648.7,1913.94) v1@2668.68,1911.23 ; U6.L14@2662.37,1892.89 cw(c2679.83,1882.81) v1@2677.12,1902.79 ; 2665.66,1900.46 ccw(c2662.21,1906.44) v1@2668.87,1908.25 ; 2666.35,1899.77 cw(c2672.33,1896.32) v1@2674.14,1902.98 ; 2667.47,1901.72 cw(c2678.1,1895.58) v1@2676.45,1907.74 ; 2667.61,1901.58 ccw(c2661.47,1912.21) v1@2673.63,1910.56 ; v1@2668.61,1910.22 cw(c2650.5,1910.22) 2663.31,1897.42 cw(c2676.11,1884.61) v1@2676.11,1902.72 ; v1@2674.17,1902.98 ccw(c2672.34,1896.15) 2668.81,1902.27 cw(c2672.34,1896.15) v1@2674.17,1902.98 ; 2668.16,1902.92 ccw(c2662.04,1906.45) 2668.87,1908.28 cw(c2662.04,1906.45) 2668.16,1902.92
  Mid-Layer 1 w5: v1(2676.11,1910.22) 2676.11,1918.11 2694,1936 ; v1@2678.61,1910.26 cw(c2702.66,1910.65) 2685.65,1927.65 ; v1@2683.61,1910.34 cw(c2719.09,1910.91) 2694,1936 ; J5.4@3183.89,2990.06 cw(c3137.75,2943.92) 3203,2943.92 cw(c3268.25,2943.92) J5.4@3222.11,2990.06 ; J5.4@3187.42,2993.6 cw(c3149.82,2955.99) 3203,2955.99 cw(c3256.18,2955.99) J5.4@3218.58,2993.6 ; J5.4@3190.96,2997.13 cw(c3161.89,2968.07) 3203,2968.07 cw(c3244.11,2968.07) J5.4@3215.04,2997.13 ; J5.4@3203,3009 3203,2525 2694,2016 2694,1936
L16: RN1.4 U6.L16 | length 2153.1
  Top Layer w5: U6.L16@2651.93,1973.77 ccw(c2641.08,1984.63) 2656.43,1984.63 ccw(c2671.78,1984.63) U6.L16@2660.92,1973.77 ; U6.L16@2656.43,1969.28 2656.43,2001.43 2924,2269 3749,2269 3867.51,2387.51 RN1.4@4573,2387.51 ; RN1.4@4557.39,2383.71 ccw(c4548.22,2374.54) 4548.22,2387.51 ccw(c4548.22,2400.49) RN1.4@4557.39,2391.31
LED0: RN34.4 U6.P4 | length 1610.1
  Top Layer w5: U6.P4@2774.54,1490.48 cw(c2774.54,1475.13) 2785.39,1485.98 cw(c2796.24,1496.83) U6.P4@2780.89,1496.83 ; U6.P4@2774.54,1496.83 v1(2794.22,1477.15) ; U6.P4@2776.89,1490.89 cw(c2766.81,1473.43) v1@2786.79,1476.14 ; U6.P4@2780.48,1494.48 ccw(c2797.94,1504.56) v1@2795.23,1484.58 ; 2783.77,1486.91 cw(c2780.32,1480.93) v1@2786.98,1479.12 ; 2784.46,1487.6 ccw(c2790.44,1491.05) v1@2792.25,1484.39 ; 2785.58,1485.65 ccw(c2796.21,1491.79) v1@2794.56,1479.63 ; 2785.72,1485.79 cw(c2779.58,1475.16) v1@2791.74,1476.81 ; v1@2786.72,1477.15 ccw(c2768.61,1477.15) 2781.42,1489.95 ccw(c2794.22,1502.76) v1@2794.22,1484.65 ; v1@3928.7,1186.7 cw(c3917.07,1175.07) RN34.4@3933.51,1175.07 ; RN34.4@3929.71,1174.61 ccw(c3920.54,1183.78) 3933.51,1183.78 ccw(c3946.49,1183.78) RN34.4@3937.31,1174.61 ; v1@3930.26,1185.5 cw(c3927.85,1181.32) 3932.52,1180.07 cw(c3939.82,1178.11) v1@3936.9,1185.08 ; v1@3931.08,1185.09 cw(c3929.06,1180.3) 3934.09,1181.64 ; RN34.4@3933.51,1159 v1@3933.51,1192 ; RN34.4@3933.51,1172.71 cw(c3953.29,1172.71) v1@3939.3,1186.7 ; v1@2786.98,1479.09 ccw(c2780.15,1480.92) 2786.27,1484.45 cw(c2780.15,1480.92) v1@2786.98,1479.09 ; 2786.92,1485.1 ccw(c2790.45,1491.22) 2792.28,1484.39 cw(c2790.45,1491.22) 2786.92,1485.1
  Mid-Layer 1 w5: v1@2794.22,1469.65 cw(c2794.22,1435.54) 2818.34,1459.66 ; v1@2794.22,1474.65 cw(c2794.22,1452.61) 2809.81,1468.19 ; v1(2794.22,1477.15) 2800.85,1477.15 2819,1459 3045,1459 3312,1192 v1(3934,1192) ; v1@3928.7,1186.7 ccw(c3915.89,1173.89) 3915.89,1192 ccw(c3915.89,1210.11) v1@3928.7,1197.3
LED1: RN34.3 U6.N5 | length 1704.5
  Top Layer w5: U6.N5@2735.17,1529.85 cw(c2735.17,1514.5) 2746.02,1525.35 cw(c2756.87,1536.2) U6.N5@2741.52,1536.2 ; U6.N5@2735.17,1536.2 v1(2754.85,1516.52) ; U6.N5@2737.52,1530.26 cw(c2727.44,1512.8) v1@2747.42,1515.51 ; U6.N5@2741.11,1533.85 ccw(c2758.57,1543.93) v1@2755.86,1523.95 ; 2744.4,1526.28 cw(c2740.95,1520.3) v1@2747.61,1518.49 ; 2745.09,1526.97 ccw(c2751.07,1530.42) v1@2752.88,1523.76 ; 2746.21,1525.02 ccw(c2756.84,1531.16) v1@2755.19,1519 ; 2746.35,1525.16 cw(c2740.21,1514.53) v1@2752.37,1516.18 ; v1@2747.35,1516.52 ccw(c2729.24,1516.52) 2742.05,1529.32 ccw(c2754.85,1542.13) v1@2754.85,1524.02 ; v1@3959.7,1186.7 cw(c3946.87,1173.87) 3965.01,1173.87 cw(c3983.09,1173.91) v1@3970.3,1186.7 ; RN34.3@3961.21,1174.61 ccw(c3952.03,1183.78) 3965.01,1183.78 ccw(c3977.98,1183.78) RN34.3@3968.81,1174.61 ; v1@3962.09,1185.09 cw(c3959.62,1179.19) 3965.8,1180.84 cw(c3969.25,1181.77) 3967.88,1185.07 ccw(c3970.37,1179.22) 3964.23,1180.87 ccw(c3960.8,1181.79) v1@3962.15,1185.06 ; RN34.3@3965.01,1159 v1(3965,1192) ; v1@2752.91,1523.76 cw(c2751.08,1530.59) 2747.55,1524.47 ccw(c2751.08,1530.59) v1@2752.91,1523.76 ; 2746.9,1523.82 cw(c2740.78,1520.29) 2747.61,1518.46 ccw(c2740.78,1520.29) 2746.9,1523.82
  Mid-Layer 1 w5: v1@2754.85,1509.02 cw(c2754.85,1472.49) 2780.68,1498.32 ; v1@2754.85,1514.02 cw(c2754.85,1489.56) 2772.14,1506.86 ; v1(2754.85,1516.52) 2762.48,1516.52 2782,1497 3040,1497 3327,1210 3947,1210 v1(3965,1192) ; v1@3957.5,1192 ccw(c3939.39,1192) 3952.2,1204.8 ccw(c3965,1217.61) v1@3965,1199.5
LED2: RN34.2 U6.P5 | length 1680.2
  Top Layer w5: U6.P5@2774.54,1529.85 cw(c2774.54,1514.5) 2785.39,1525.35 cw(c2796.24,1536.2) U6.P5@2780.89,1536.2 ; U6.P5@2774.54,1536.2 v1(2794.22,1516.52) ; U6.P5@2776.89,1530.26 cw(c2766.81,1512.8) v1@2786.79,1515.51 ; U6.P5@2780.48,1533.85 ccw(c2797.94,1543.93) v1@2795.23,1523.95 ; 2783.77,1526.28 cw(c2780.32,1520.3) v1@2786.98,1518.49 ; 2784.46,1526.97 ccw(c2790.44,1530.42) v1@2792.25,1523.76 ; 2785.58,1525.02 ccw(c2796.21,1531.16) v1@2794.56,1519 ; 2785.72,1525.16 cw(c2779.58,1514.53) v1@2791.74,1516.18 ; v1@2786.72,1516.52 ccw(c2768.61,1516.52) 2781.42,1529.32 ccw(c2794.22,1542.13) v1@2794.22,1524.02 ; v1@3990.7,1185.7 cw(c3976.68,1171.68) RN34.2@3996.5,1171.68 ; RN34.2@3992.7,1174.61 ccw(c3983.53,1183.78) 3996.5,1183.78 ccw(c4009.48,1183.78) RN34.2@4000.3,1174.61 ; v1@3993.6,1183.89 cw(c3991.61,1178) 3997.62,1179.61 cw(c4001.76,1180.72) v1@3999.67,1184.46 ; RN34.2@3996.5,1159 v1@3996.5,1191 ; RN34.2@3996.5,1174.11 cw(c4012.89,1174.11) v1@4001.3,1185.7 ; 2786.27,1523.82 cw(c2780.15,1520.29) 2786.98,1518.46 ccw(c2780.15,1520.29) 2786.27,1523.82 ; 2786.92,1524.47 ccw(c2790.45,1530.59) 2792.28,1523.76 cw(c2790.45,1530.59) 2786.92,1524.47
  Mid-Layer 1 w5: v1(2794.22,1516.52) 2797.74,1513 3046,1513 3333,1226 3961,1226 v1(3996,1191) ; v1@2795.99,1518.29 ccw(c2808.75,1531.05) 2808.75,1513 ; v1@2799.52,1511.22 cw(c2803.83,1506.91) 2803.83,1513 ; v1@2799.52,1521.82 ccw(c2820.82,1543.12) 2820.82,1513 ; v1@3988.5,1191 ccw(c3970.39,1191) 3983.2,1203.8 ccw(c3996,1216.61) v1@3996,1198.5
LED3: RN34.1 U6.M6 | length 1789.8
  Top Layer w5: U6.M6@2695.8,1569.22 cw(c2695.8,1553.87) 2706.65,1564.72 cw(c2717.5,1575.57) U6.M6@2702.15,1575.57 ; U6.M6@2695.8,1575.57 v1(2715.48,1555.89) ; U6.M6@2698.15,1569.63 cw(c2688.07,1552.17) v1@2708.05,1554.88 ; U6.M6@2701.74,1573.22 ccw(c2719.2,1583.3) v1@2716.49,1563.32 ; 2705.03,1565.65 cw(c2701.58,1559.67) v1@2708.24,1557.86 ; 2705.72,1566.34 ccw(c2711.7,1569.79) v1@2713.51,1563.13 ; 2706.84,1564.39 ccw(c2717.47,1570.53) v1@2715.82,1558.37 ; 2706.98,1564.53 cw(c2700.84,1553.9) v1@2713,1555.55 ; v1@2707.98,1555.89 ccw(c2689.87,1555.89) 2702.68,1568.69 ccw(c2715.48,1581.5) v1@2715.48,1563.39 ; v1@4021.7,1185.7 cw(c4008.89,1172.89) 4027,1172.89 cw(c4045.11,1172.89) v1@4032.3,1185.7 ; RN34.1@4024.2,1174.61 ccw(c4017.44,1181.37) v1@4027,1181.37 ; v1@4024.98,1183.78 cw(c4023.58,1178.73) 4028.64,1180.08 cw(c4032.26,1181.06) v1@4030.51,1184.37 ; RN34.1@4027,1160 v1(4027,1191) ; v1@4027,1186.2 ccw(c4043.39,1186.2) RN34.1@4031.8,1174.61 ; v1@2708.24,1557.83 ccw(c2701.41,1559.66) 2707.53,1563.19 cw(c2701.41,1559.66) v1@2708.24,1557.83 ; 2708.18,1563.84 ccw(c2711.71,1569.96) 2713.54,1563.13 cw(c2711.71,1569.96) 2708.18,1563.84
  Mid-Layer 1 w5: v1@2715.48,1548.39 cw(c2715.48,1530.28) 2728.28,1543.09 cw(c2741.09,1555.89) v1@2722.98,1555.89 ; v1(2715.48,1555.89) 2736.37,1535 2804,1535 2813,1526 3056,1526 3339,1243 3975,1243 v1(4027,1191) ; v1@4019.5,1191 ccw(c4001.39,1191) 4014.2,1203.8 ccw(c4027,1216.61) v1@4027,1198.5
LED_A: RN14.2 U13.11 | length 834.8
  Top Layer w12: U13.11@1495,918 cw(c1495,860.06) 1535.97,901.03 cw(c1576.94,942) U13.11@1519,942 ; U13.11@1495,942 1611,826 1803,826 1872.5,895.5 RN14.2@1872.5,1185
LED_B: RN10.4 U13.7 | length 898.4
  Top Layer w12: U13.7@1795,542 1856,542 2105.49,791.49 RN10.4@2105.49,1185 ; U13.7@1811.97,525.03 cw(c1852.94,484.06) 1852.94,542 cw(c1852.94,599.94) U13.7@1811.97,558.97
LED_C: RN10.2 U13.4 | length 1109.6
  Top Layer w12: U13.4@1495,542 1586,633 1840,633 2042.5,835.5 RN10.2@2042.5,1185 ; U13.4@1495,566 ccw(c1495,623.94) 1535.97,582.97 ccw(c1576.94,542) U13.4@1519,542
LED_D: RN14.3 U13.1 | length 1252.6
  Top Layer w12: U13.1@1195,542 1431,778 1815,778 1903.99,866.99 RN14.3@1903.99,1185 ; U13.1@1195,566 ccw(c1195,623.94) 1235.97,582.97 ccw(c1276.94,542) U13.1@1219,542
LED_E: RN10.1 U13.3 | length 1164.9
  Top Layer w12: U13.3@1395,542 1529,676 1829,676 2011,858 RN10.1@2011,1185 ; U13.3@1395,566 ccw(c1395,623.94) 1435.97,582.97 ccw(c1476.94,542) U13.3@1419,542
LED_F: RN14.1 U13.10 | length 643.7
  Top Layer w12: U13.10@1595,918 cw(c1595,860.06) 1635.97,901.03 cw(c1676.94,942) U13.10@1619,942 ; U13.10@1595,942 1657,880 1800,880 1841,921 RN14.1@1841,1185
LED_G: RN10.3 U13.6 | length 956.6
  Top Layer w12: U13.6@1695,542 1749,596 1861,596 2073.99,808.99 RN10.3@2073.99,1185 ; U13.6@1695,566 ccw(c1695,623.94) 1735.97,582.97 ccw(c1776.94,542) U13.6@1719,542
LED_H: RN14.4 U13.2 | length 1202
  Top Layer w12: U13.2@1295,542 1483,730 1829,730 1935.49,836.49 RN14.4@1935.49,1185 ; U13.2@1295,566 ccw(c1295,623.94) 1335.97,582.97 ccw(c1376.94,542) U13.2@1319,542
M0: R50.1 U6.T11 | length 293.7
  Top Layer w5: U6.T11@2853.28,1772.43 2981.57,1772.43 R50.1@2989,1765 ; U6.T11@2857.77,1767.93 cw(c2868.63,1757.08) 2868.63,1772.43 cw(c2868.63,1787.78) U6.T11@2857.77,1776.92 ; 2938.48,1772.43 cw(c2938.48,1714.48) R50.1@2979.45,1755.45 ; 2950.55,1772.43 cw(c2950.55,1726.55) R50.1@2982.99,1758.99 ; 2962.62,1772.43 cw(c2962.62,1738.62) R50.1@2986.53,1762.53 ; R50.1@2974.33,1772.43 ccw(c2974.33,1779.67) R50.1@2979.45,1774.55 ; R50.1@2974.7,1772.43 cw(c2974.7,1750.7) R50.1@2990.06,1766.06
M1: R51.1 U6.N11 | length 352
  Top Layer w5: U6.N11@2735.17,1772.43 v1(2754.85,1792.11) ; U6.N11@2735.17,1778.78 ccw(c2735.17,1794.13) 2746.02,1783.28 ccw(c2756.87,1772.43) U6.N11@2741.52,1772.43 ; U6.N11@2737.52,1778.37 ccw(c2727.44,1795.83) v1@2747.42,1793.12 ; U6.N11@2741.11,1774.78 cw(c2758.57,1764.7) v1@2755.86,1784.68 ; 2744.4,1782.35 ccw(c2740.95,1788.33) v1@2747.61,1790.14 ; 2745.09,1781.66 cw(c2751.07,1778.21) v1@2752.88,1784.87 ; 2746.21,1783.61 cw(c2756.84,1777.47) v1@2755.19,1789.63 ; 2746.35,1783.47 ccw(c2740.21,1794.1) v1@2752.37,1792.45 ; v1@2747.35,1792.11 cw(c2729.24,1792.11) 2742.05,1779.31 cw(c2754.85,1766.5) v1@2754.85,1784.61 ; v1@2747.61,1790.17 cw(c2740.78,1788.34) 2746.9,1784.81 ccw(c2740.78,1788.34) v1@2747.61,1790.17 ; 2747.55,1784.16 cw(c2751.08,1778.04) 2752.91,1784.87 ccw(c2751.08,1778.04) 2747.55,1784.16
  Bottom Layer w5: v1@2754.85,1784.61 cw(c2754.85,1766.5) 2767.65,1779.31 cw(c2780.46,1792.11) v1@2762.35,1792.11 ; v1(2754.85,1792.11) 2773.96,1773 2875,1773 R51.1@2886,1762
M4: RN8.1 U6.M4 | length 2241.5
  Top Layer w5: U6.M4@2695.8,1490.48 cw(c2695.8,1475.13) 2706.65,1485.98 cw(c2717.5,1496.83) U6.M4@2702.15,1496.83 ; U6.M4@2695.8,1496.83 v1(2715,1477.63) ; U6.M4@2698.24,1490.84 cw(c2688.79,1474.47) v1@2707.55,1476.73 ; U6.M4@2701.79,1494.39 ccw(c2718.16,1503.84) v1@2715.9,1485.08 ; 2705.12,1486.86 cw(c2702.12,1481.67) v1@2707.84,1479.88 ; 2705.77,1487.51 ccw(c2710.96,1490.51) v1@2712.75,1484.79 ; 2706.8,1485.73 ccw(c2716.66,1491.42) v1@2715.3,1480.11 ; 2706.9,1485.83 cw(c2701.21,1475.97) v1@2712.52,1477.33 ; v1@2707.5,1477.63 ccw(c2689.39,1477.63) 2702.2,1490.43 ccw(c2715,1503.24) v1@2715,1485.13 ; v1(3004,1338) 3077,1338 3171,1244 4438,1244 4518.38,1324.38 RN8.1@4573,1324.38 ; v1@3009.3,1332.7 cw(c3022.11,1319.89) 3022.11,1338 cw(c3022.11,1356.11) v1@3009.3,1343.3 ; RN8.1@4557.39,1320.58 ccw(c4548.22,1311.4) 4548.22,1324.38 ccw(c4548.22,1337.35) RN8.1@4557.39,1328.17 ; 2706.99,1485.39 cw(c2700.35,1481.56) 2707.76,1479.57 ccw(c2700.35,1481.56) 2706.99,1485.39 ; 2707.24,1485.64 ccw(c2711.07,1492.28) 2713.06,1484.87 cw(c2711.07,1492.28) 2707.24,1485.64
  Bottom Layer w5: v1(2715,1477.63) 2735.63,1457 2885,1457 v1(3004,1338) ; v1@2996.5,1338 ccw(c2978.39,1338) 2991.2,1350.8 ccw(c3004,1363.61) v1@3004,1345.5
M5: RN9.2 U6.M5 | length 2343.5
  Top Layer w5: U6.M5@2695.8,1529.85 cw(c2695.8,1514.5) 2706.65,1525.35 cw(c2717.5,1536.2) U6.M5@2702.15,1536.2 ; U6.M5@2695.8,1536.2 v1(2715,1517) ; U6.M5@2698.24,1530.21 cw(c2688.79,1513.84) v1@2707.55,1516.1 ; U6.M5@2701.79,1533.76 ccw(c2718.16,1543.21) v1@2715.9,1524.45 ; 2705.12,1526.23 cw(c2702.12,1521.04) v1@2707.84,1519.25 ; 2705.77,1526.88 ccw(c2710.96,1529.88) v1@2712.75,1524.16 ; 2706.8,1525.1 ccw(c2716.66,1530.79) v1@2715.3,1519.48 ; 2706.9,1525.2 cw(c2701.21,1515.34) v1@2712.52,1516.7 ; v1@2707.5,1517 ccw(c2689.39,1517) 2702.2,1529.8 ccw(c2715,1542.61) v1@2715,1524.5 ; v1(4536,1128) RN9.2@4572.5,1128 ; v1@4541.3,1122.7 cw(c4554.11,1109.89) 4554.11,1128 cw(c4554.11,1146.11) v1@4541.3,1133.3 ; 4547.02,1128 cw(c4547.02,1113.33) RN9.2@4557.39,1123.7 ; 4549.41,1128 ccw(c4549.41,1139.28) RN9.2@4557.39,1131.3 ; 2706.99,1524.76 cw(c2700.35,1520.93) 2707.76,1518.94 ccw(c2700.35,1520.93) 2706.99,1524.76 ; 2707.24,1525.01 ccw(c2711.07,1531.65) 2713.06,1524.24 cw(c2711.07,1531.65) 2707.24,1525.01
  Mid-Layer 1 w5: v1@2715,1509.5 cw(c2715,1491.39) 2727.8,1504.2 cw(c2740.61,1517) v1@2722.5,1517 ; v1(2715,1517) 2735,1497 2735,1469 2747,1457 2765,1457 2775,1447 2775,1430 2788,1417 2854,1417 2874,1437 2977,1437 3286,1128 v1(4536,1128) ; v1@4530.7,1122.7 ccw(c4517.89,1109.89) 4517.89,1128 ccw(c4517.89,1146.11) v1@4530.7,1133.3
M15: RN2.2 U6.M15 | length 2082.8
  Top Layer w5: U6.M15@2695.8,1929.91 2715.48,1949.59 2715.48,1973.48 2958,2216 3751,2216 3820.13,2285.13 RN2.2@4573,2285.13 ; U6.M15@2695.8,1936.26 ccw(c2695.8,1951.61) 2706.65,1940.76 ccw(c2717.5,1929.91) U6.M15@2702.15,1929.91 ; RN2.2@4557.39,2281.33 ccw(c4548.22,2272.15) 4548.22,2285.13 ccw(c4548.22,2298.1) RN2.2@4557.39,2288.93
M16: RN2.1 U6.M16 | length 2091.7
  Top Layer w5: U6.M16@2691.3,1973.77 ccw(c2680.45,1984.63) 2695.8,1984.63 ccw(c2711.15,1984.63) U6.M16@2700.29,1973.77 ; U6.M16@2695.8,1969.28 2695.8,2013.8 2918,2236 3745,2236 3825.62,2316.62 RN2.1@4573,2316.62 ; RN2.1@4557.39,2312.83 ccw(c4548.22,2303.65) 4548.22,2316.62 ccw(c4548.22,2329.6) RN2.1@4557.39,2320.42
N4: RN9.1 U6.N4 | length 2308.7
  Top Layer w5: U6.N4@2735.17,1490.48 cw(c2735.17,1475.13) 2746.02,1485.98 cw(c2756.87,1496.83) U6.N4@2741.52,1496.83 ; U6.N4@2735.17,1496.83 v1(2754.85,1477.15) ; U6.N4@2737.52,1490.89 cw(c2727.44,1473.43) v1@2747.42,1476.14 ; U6.N4@2741.11,1494.48 ccw(c2758.57,1504.56) v1@2755.86,1484.58 ; 2744.4,1486.91 cw(c2740.95,1480.93) v1@2747.61,1479.12 ; 2745.09,1487.6 ccw(c2751.07,1491.05) v1@2752.88,1484.39 ; 2746.21,1485.65 ccw(c2756.84,1491.79) v1@2755.19,1479.63 ; 2746.35,1485.79 cw(c2740.21,1475.16) v1@2752.37,1476.81 ; v1@2747.35,1477.15 ccw(c2729.24,1477.15) 2742.05,1489.95 ccw(c2754.85,1502.76) v1@2754.85,1484.65 ; v1(4538,1158) RN9.1@4572,1158 ; v1@4543.3,1152.7 cw(c4556.11,1139.89) 4556.11,1158 cw(c4556.11,1176.11) v1@4543.3,1163.3 ; v1@4544.46,1161.81 ccw(c4549.19,1164.6) 4550.62,1159.29 ccw(c4553.09,1150.07) v1@4544.64,1154.51 ; v1@4545.8,1158 ccw(c4545.8,1174.39) RN9.1@4557.39,1162.8 ; 4550.63,1158 cw(c4550.63,1148.44) RN9.1@4557.39,1155.2 ; v1@2747.61,1479.09 ccw(c2740.78,1480.92) 2746.9,1484.45 cw(c2740.78,1480.92) v1@2747.61,1479.09 ; v1@2752.91,1484.39 cw(c2751.08,1491.22) 2747.55,1485.1 ccw(c2751.08,1491.22) v1@2752.91,1484.39
  Mid-Layer 1 w5: v1@2754.85,1469.65 cw(c2754.85,1424.99) 2786.43,1456.57 ; v1@2754.85,1474.65 cw(c2754.85,1442.06) 2777.9,1465.1 ; v1(2754.85,1477.15) 2765.85,1477.15 ; v1@2754.85,1479.65 cw(c2754.85,1459.13) 2769.36,1473.64 ; v1@2761.83,1474.41 cw(c2765.85,1472.83) 2765.85,1477.15 ; v1@2761.83,1479.89 ccw(c2765.85,1481.46) 2765.85,1477.15 ; v1@4532.7,1152.7 ccw(c4519.89,1139.89) 4519.89,1158 ccw(c4519.89,1176.11) v1@4532.7,1163.3 ; v1(4538,1158) 3280,1158 2989,1449 2811,1449 2804,1456 2787,1456 2765.85,1477.15
N6: RN8.3 U6.N6 | length 2253
  Top Layer w5: U6.N6@2735.17,1569.22 cw(c2735.17,1553.87) 2746.02,1564.72 cw(c2756.87,1575.57) U6.N6@2741.52,1575.57 ; U6.N6@2735.17,1575.57 v1(2754.85,1555.89) ; U6.N6@2737.52,1569.63 cw(c2727.44,1552.17) v1@2747.42,1554.88 ; U6.N6@2741.11,1573.22 ccw(c2758.57,1583.3) v1@2755.86,1563.32 ; 2744.4,1565.65 cw(c2740.95,1559.67) v1@2747.61,1557.86 ; 2745.09,1566.34 ccw(c2751.07,1569.79) v1@2752.88,1563.13 ; 2746.21,1564.39 ccw(c2756.84,1570.53) v1@2755.19,1558.37 ; 2746.35,1564.53 cw(c2740.21,1553.9) v1@2752.37,1555.55 ; v1@2747.35,1555.89 ccw(c2729.24,1555.89) 2742.05,1568.69 ccw(c2754.85,1581.5) v1@2754.85,1563.39 ; v1(4536,1261) RN8.3@4572.62,1261 ; v1@4541.3,1255.7 cw(c4554.11,1242.89) 4554.11,1261 cw(c4554.11,1279.11) v1@4541.3,1266.3 ; 4547.29,1261 ccw(c4547.29,1275.28) RN8.3@4557.39,1265.18 ; 4549.14,1261 cw(c4549.14,1249.33) RN8.3@4557.39,1257.58 ; v1@2747.61,1557.83 ccw(c2740.78,1559.66) 2746.9,1563.19 cw(c2740.78,1559.66) v1@2747.61,1557.83 ; v1@2752.91,1563.13 cw(c2751.08,1569.96) 2747.55,1563.84 ccw(c2751.08,1569.96) v1@2752.91,1563.13
  Mid-Layer 1 w5: v1(2754.85,1555.89) 2774.96,1576 3051,1576 3344,1283 3985,1283 4020,1248 4523,1248 v1(4536,1261) ; v1@2754.85,1563.39 ccw(c2754.85,1581.5) 2767.65,1568.69 ccw(c2780.46,1555.89) v1@2762.35,1555.89 ; v1@4528.5,1261 cw(c4510.39,1261) 4523.2,1248.2 cw(c4536,1235.39) v1@4536,1253.5
N16: RN2.3 U6.N16 | length 2000.1
  Top Layer w5: U6.N16@2735.17,1969.28 2962.89,2197 3763,2197 3819.63,2253.63 RN2.3@4573,2253.63 ; U6.N16@2735.17,1975.63 ccw(c2735.17,1990.98) 2746.02,1980.13 ccw(c2756.87,1969.28) U6.N16@2741.52,1969.28 ; RN2.3@4557.39,2249.83 ccw(c4548.22,2240.66) 4548.22,2253.63 ccw(c4548.22,2266.61) RN2.3@4557.39,2257.43
NetC1_1: C1.1 C2.1 R2.2 U4.6 | length 555.5
  Top Layer w5: C1.1@567,2883 C1.1@576,2892
  Top Layer w10: R2.2@494,2810 C1.1@565.5,2881.5 ; R2.2@494,2821 ccw(c494,2847.56) 512.78,2828.78 ccw(c531.56,2810) R2.2@505,2810 ; 543.1,2859.1 ccw(c519.2,2883) C1.1@553,2883 ; C2.1@549.22,2932.11 cw(c513.55,2896.43) C1.1@564,2896.43 ; 550.34,2866.34 cw(c564,2852.69) C1.1@564,2872 ; C1.1@556.22,2890.78 ccw(c537.44,2909.56) 564,2909.56 ccw(c590.56,2909.56) 571.78,2890.78 ccw(c590.56,2909.56) 590.56,2883 ccw(c590.56,2856.44) C1.1@571.78,2875.22 ; C2.1@556.3,2939.18 cw(c537.69,2920.58) 564,2920.58 ; C1.1@564,2883 564,2936 C2.1@576,2948 ; 564,2910.92 cw(c593.96,2910.92) C2.1@572.78,2932.11 ; C1.1@567,2883 603,2883 641.57,2844.43 U4.6@641.57,2814
NetC3_1: C3.1 C46.1 L1.2 R75.2 X1.4 | length 517.3
  Top Layer w20: X1.4@3565,1452 3653,1452 ; X1.4@3580.2,1436.8 cw(c3616.9,1400.1) 3616.9,1452 cw(c3616.9,1503.9) X1.4@3580.2,1467.2 ; L1.2@3675,1430 3675,1520 ccw(c3694.62,1520) C46.1@3690.32,1500.85 ; L1.2@3675,1446.72 cw(c3737.28,1446.72) C46.1@3693.24,1490.76 ; C46.1@3675,1482.28 ccw(c3737.28,1482.28) L1.2@3693.24,1438.24 ; C3.1@3678,1551 3678,1560 3699.67,1581.67 3714.67,1581.67 R75.2@3755,1622 ; C3.1@3680.5,1551 cw(c3708.26,1551) 3688.63,1570.63
NetC41_1: C41.1 J4.13 R30.1 | length 1533.6
  Top Layer w12: R30.1@3315,2843 3430,2958 3430,3130 3591,3291 4076,3291 J4.13@4135,3232 ; R30.1@3315,2853 ccw(c3315,2877.14) 3332.07,2860.07 ccw(c3349.14,2843) R30.1@3325,2843 ; J4.13@4107,3232 ccw(c4039.4,3232) 4087.2,3279.8 ccw(c4135,3327.6) J4.13@4135,3260 ; J4.13@4119,3232 ccw(c4080.37,3232) 4107.69,3259.31 ccw(c4135,3286.63) J4.13@4135,3248
  Bottom Layer w20: J4.13@4118.03,3248.97 ccw(c4077.06,3289.94) 4135,3289.94 ccw(c4192.94,3289.94) J4.13@4151.97,3248.97 ; J4.13@4135,3232 C41.1@4135,3339
NetC42_1: C42.1 J4.14 R31.1 | length 1730.3
  Top Layer w12: R31.1@3244,2843 3387,2986 3387,3148 3579,3340 4117,3340 J4.14@4225,3232 ; R31.1@3244,2853 ccw(c3244,2877.14) 3261.07,2860.07 ccw(c3278.14,2843) R31.1@3254,2843 ; J4.14@4197,3232 ccw(c4129.4,3232) 4177.2,3279.8 ccw(c4225,3327.6) J4.14@4225,3260 ; J4.14@4209,3232 ccw(c4170.37,3232) 4197.69,3259.31 ccw(c4225,3286.63) J4.14@4225,3248
  Bottom Layer w20: J4.14@4208.03,3248.97 ccw(c4167.06,3289.94) 4225,3289.94 ccw(c4282.94,3289.94) J4.14@4241.97,3248.97 ; J4.14@4225,3232 C42.1@4225,3340
NetCB1_2: CB1.2 R33.1 | length 317.5
  Top Layer w10: R33.1@2590,2264 2628,2302 ; R33.1@2590,2275 ccw(c2590,2301.56) 2608.78,2282.78 ccw(c2627.56,2264) R33.1@2601,2264 ; CB1.2@2670.19,2282.88 ccw(c2628,2245.89) 2628,2302 ; CB1.2@2670.19,2321.12 cw(c2628,2358.11) 2628,2302 ; CB1.2@2677.71,2289.47 ccw(c2650.07,2265.24) 2650.07,2302 ccw(c2650.07,2338.76) CB1.2@2677.71,2314.53 ; CB1.2@2692,2302 2628,2302
NetD1_2: D1.2 LS1.1 R34.2 | length 614.1
  Top Layer w15: D1.2@2452,2548 2507,2603 R34.2@2559,2603 2733,2603 LS1.1@2734,2602 ; D1.2@2452,2570.5 ccw(c2452,2624.82) 2490.41,2586.41 ccw(c2528.82,2548) D1.2@2474.5,2548 ; R34.2@2552.99,2596.99 ccw(c2538.48,2582.48) 2538.48,2603 ccw(c2538.48,2623.52) R34.2@2552.99,2609.01 ; R34.2@2565.01,2596.99 cw(c2579.52,2582.48) 2579.52,2603 cw(c2579.52,2623.52) R34.2@2565.01,2609.01 ; 2653.12,2603 cw(c2653.12,2521.12) LS1.1@2711.02,2579.02 ; 2657.95,2603 ccw(c2657.95,2678.05) LS1.1@2711.02,2624.98 ; 2689.34,2603 cw(c2689.34,2557.34) LS1.1@2721.63,2589.63
NetF1_2: F1.2 SW1.2 SW1.5
NetK1_1: K1.1 R38.2 R46.2 | length 754
  Top Layer w5: K1.1@1724.28,120.72 ccw(c1681.5,163.5) 1742,163.5 ccw(c1802.5,163.5) K1.1@1759.72,120.72 ; K1.1@1727.82,117.18 ccw(c1693.57,151.43) 1742,151.43 ccw(c1790.43,151.43) K1.1@1756.18,117.18 ; K1.1@1731.35,113.65 ccw(c1705.64,139.36) 1742,139.36 ccw(c1778.36,139.36) K1.1@1752.65,113.65 ; v1@1735.95,165.57 cw(c1718.6,152.87) 1739.85,149.58 ; v1@1736.7,164.7 cw(c1723.89,151.89) 1742,151.89 cw(c1760.11,151.89) v1@1747.3,164.7 ; v1@1737.57,163.95 cw(c1728.88,152.08) 1743.42,154.33 ; 1740.58,154.33 cw(c1755.12,152.08) v1@1746.43,163.95 ; K1.1@1742,103 v1(1742,170) ; 1744.15,149.58 cw(c1765.4,152.87) v1@1748.05,165.57
  Bottom Layer w6: R46.2@1731.81,221.81 cw(c1709.62,199.62) 1741,199.62 cw(c1772.38,199.62) 1750.19,221.81 cw(c1772.38,199.62) 1772.38,231 cw(c1772.38,262.38) R46.2@1750.19,240.19 ; R46.2@1736.05,226.05 cw(c1724.1,214.1) 1741,214.1 cw(c1757.9,214.1) 1745.95,226.05 cw(c1757.9,214.1) 1757.9,231 cw(c1757.9,247.9) R46.2@1745.95,235.95 ; v1@1737.05,174.95 ccw(c1727.51,184.49) 1741,184.49 ; 1741,189.31 ccw(c1761.31,189.31) v1@1746.95,174.95 ; v1(1742,170) 1741,171 R46.2@1741,231 R38.2@1799,231 ; R38.2@1789.81,221.81 ccw(c1767.62,199.62) 1767.62,231 ccw(c1767.62,262.38) R38.2@1789.81,240.19 ; R38.2@1794.05,226.05 ccw(c1782.1,214.1) 1782.1,231 ccw(c1782.1,247.9) R38.2@1794.05,235.95
NetK2_1: K2.1 R37.2 R44.2 | length 749.3
  Top Layer w5: K2.1@2291.95,120.72 ccw(c2245.95,166.72) 2311,166.72 ; K2.1@2295.48,117.18 ccw(c2258.02,154.65) 2311,154.65 ; K2.1@2299.02,113.65 ccw(c2270.09,142.57) 2311,142.57 ; v1@2305.7,187.7 cw(c2292.89,174.89) 2311,174.89 cw(c2329.11,174.89) v1@2316.3,187.7 ; K2.1@2309.67,103 2311,104.33 v1(2311,193) ; 2311,136.14 ccw(c2342.8,136.14) K2.1@2320.31,113.65 ; 2311,148.21 ccw(c2354.87,148.21) K2.1@2323.85,117.18 ; 2311,160.28 ccw(c2366.95,160.28) K2.1@2327.39,120.72
  Bottom Layer w6: R44.2@2301.81,221.81 cw(c2279.62,199.62) 2311,199.62 cw(c2342.38,199.62) 2320.19,221.81 cw(c2342.38,199.62) 2342.38,231 cw(c2342.38,262.38) R44.2@2320.19,240.19 ; v1@2305.11,196.79 ccw(c2288.67,207.38) 2307.56,212.44 ; v1@2306.05,197.95 ccw(c2294.1,209.9) 2311,209.9 ccw(c2327.9,209.9) v1@2315.95,197.95 ; R44.2@2306.05,226.05 cw(c2294.1,214.1) 2311,214.1 cw(c2327.9,214.1) 2315.95,226.05 cw(c2327.9,214.1) 2327.9,231 cw(c2327.9,247.9) R44.2@2315.95,235.95 ; v1@2307.5,199.06 ccw(c2301.97,208.64) 2312.65,205.77 ; 2309.35,205.77 ccw(c2320.03,208.64) v1@2314.5,199.06 ; v1(2311,193) R44.2@2311,231 R37.2@2371,231 ; 2314.44,212.44 ccw(c2333.33,207.38) v1@2316.89,196.79 ; R37.2@2361.81,221.81 ccw(c2339.62,199.62) 2339.62,231 ccw(c2339.62,262.38) R37.2@2361.81,240.19 ; R37.2@2366.05,226.05 ccw(c2354.1,214.1) 2354.1,231 ccw(c2354.1,247.9) R37.2@2366.05,235.95
NetK3_2: K3.2 R36.2 R40.2 | length 690.3
  Top Layer w5: K3.2@2859.61,117.92 ccw(c2816.84,160.7) 2877.33,160.7 ccw(c2937.83,160.7) K3.2@2895.05,117.92 ; K3.2@2863.15,114.39 ccw(c2828.91,148.63) 2877.33,148.63 ccw(c2925.76,148.63) K3.2@2891.52,114.39 ; K3.2@2866.68,110.85 ccw(c2840.98,136.56) 2877.33,136.56 ccw(c2913.69,136.56) K3.2@2887.98,110.85 ; v1@2872.03,179.36 cw(c2859.23,166.56) 2877.33,166.56 cw(c2895.44,166.56) v1@2882.64,179.36 ; K3.2@2877.33,100.2 v1(2877.33,184.67)
  Bottom Layer w6: R40.2@2868.81,221.81 cw(c2848.22,201.22) 2877.33,201.22 ; v1@2872.38,189.62 ccw(c2860.43,201.57) 2877.33,201.57 ccw(c2894.23,201.57) v1@2882.28,189.62 ; v1(2877.33,184.67) 2877.33,230.33 R40.2@2878,231 R36.2@2938,231 ; 2877.33,198.01 cw(c2910.99,198.01) 2887.19,221.81 cw(c2909.38,199.62) 2909.38,231 cw(c2909.38,262.38) R40.2@2887.19,240.19 ; 2877.33,212.49 cw(c2896.51,212.49) 2882.95,226.05 cw(c2894.9,214.1) 2894.9,231 cw(c2894.9,247.9) R40.2@2882.95,235.95 ; R36.2@2928.81,221.81 ccw(c2906.62,199.62) 2906.62,231 ccw(c2906.62,262.38) R36.2@2928.81,240.19 ; R36.2@2933.05,226.05 ccw(c2921.1,214.1) 2921.1,231 ccw(c2921.1,247.9) R36.2@2933.05,235.95
NetK4_1: K4.1 R35.2 R39.2 | length 697.7
  Top Layer w5: K4.1@3427.28,120.72 ccw(c3384.5,163.5) 3445,163.5 ; K4.1@3430.82,117.18 ccw(c3396.57,151.43) 3445,151.43 ccw(c3493.43,151.43) K4.1@3459.18,117.18 ; K4.1@3434.35,113.65 ccw(c3408.64,139.36) 3445,139.36 ccw(c3481.36,139.36) K4.1@3455.65,113.65 ; v1@3440.7,178.7 cw(c3430.31,168.31) 3445,168.31 ; K4.1@3445,103 v1@3445,183 ; v1@3451.3,178.7 ccw(c3466.52,163.48) 3445,163.48 ; K4.1@3462.72,120.72 cw(c3505.5,163.5) 3445,163.5
  Bottom Layer w6: R39.2@3436.81,221.81 cw(c3414.62,199.62) 3446,199.62 cw(c3477.38,199.62) 3455.19,221.81 cw(c3477.38,199.62) 3477.38,231 cw(c3477.38,262.38) R39.2@3455.19,240.19 ; v1@3441.05,188.95 ccw(c3429.1,200.9) 3446,200.9 ccw(c3462.9,200.9) v1@3450.95,188.95 ; R39.2@3441.05,226.05 cw(c3429.1,214.1) 3446,214.1 cw(c3462.9,214.1) 3450.95,226.05 cw(c3462.9,214.1) 3462.9,231 cw(c3462.9,247.9) R39.2@3450.95,235.95 ; v1(3446,184) R39.2@3446,231 R35.2@3506,231 ; R35.2@3496.81,221.81 ccw(c3474.62,199.62) 3474.62,231 ccw(c3474.62,262.38) R35.2@3496.81,240.19 ; R35.2@3501.05,226.05 ccw(c3489.1,214.1) 3489.1,231 ccw(c3489.1,247.9) R35.2@3501.05,235.95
